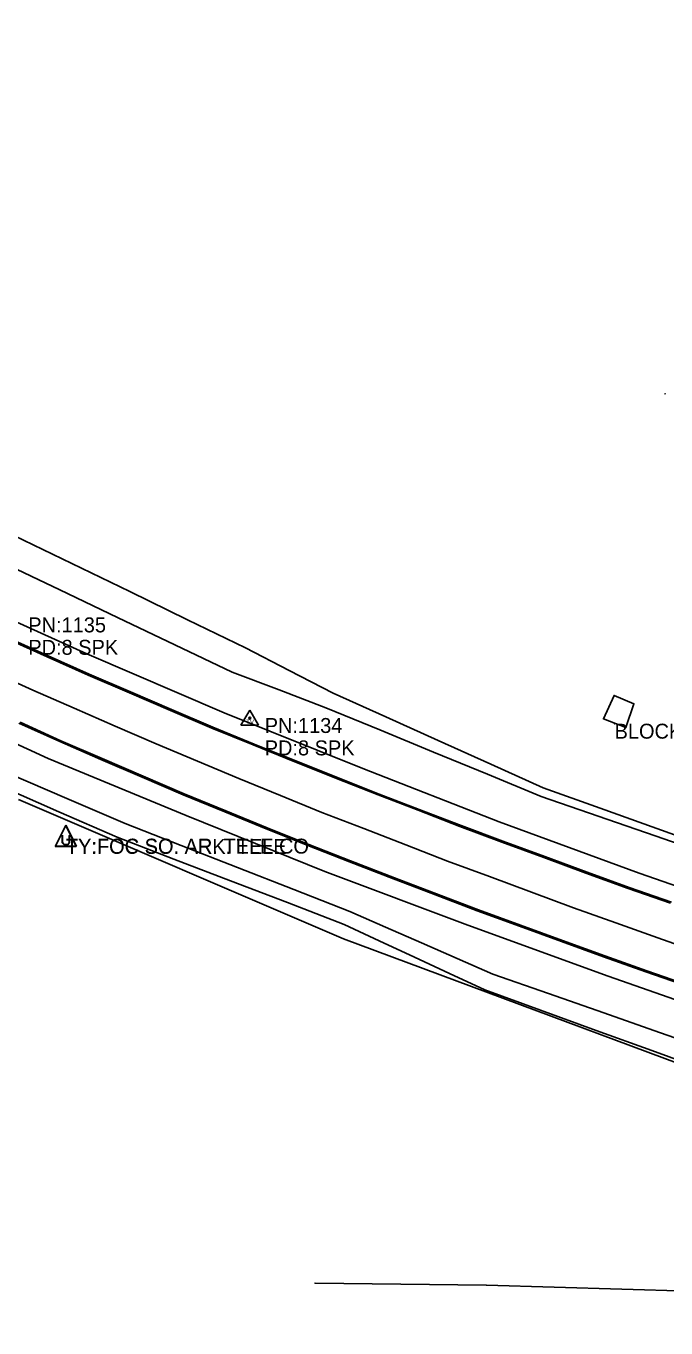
# Model space of a CAD drawing. Extents: x 878399 to 889864, y 1564003 to 1567413.
# Drawn here: x 885851.5 to 886065.8, y 1564498.7 to 1564934.4 of the extents above; entities that cross this region are included whole.
import ezdxf

# ---------------------------------------------------------------- set-up
doc = ezdxf.new("R2010")
doc.units = 0
for name, color, linetype in [('S_BUILDING', 7, 'Continuous'), ('S_DITCHLINE', 7, 'Continuous'), ('S_EDGE_PAVEMENT', 7, 'Continuous'), ('S_FENCE', 7, 'Continuous'), ('S_FIBER_OPTIC_CABLE', 7, 'Continuous'), ('S_MSC_PT_SYM', 7, 'Continuous'), ('S_PAVEMENT_CROWN', 7, 'Continuous'), ('S_SECONDARY_CTL', 7, 'Continuous'), ('S_SECONDARY_CTL_ANNOT', 7, 'Continuous'), ('S_SHOULDER', 7, 'Continuous'), ('S_STR_PT_SYM', 7, 'Continuous'), ('S_SURVEY_TEXT_ANNOT', 7, 'Continuous'), ('S_UTILITY_POLE', 7, 'Continuous'), ('S_UTILITY_POLE_ANNOT', 7, 'Continuous'), ('S_UTL_PT_SYM', 7, 'Continuous')]:
    doc.layers.add(name, color=color, linetype=linetype)

msp = doc.modelspace()

# ---------------------------------------------------------------- linework, layer by layer
at = {"layer": 'S_BUILDING'}
for p, q in [((886044.86, 1564702.57), (886048.48, 1564710.41)), ((886048.48, 1564710.41), (886055.08, 1564707.59)), ((886055.08, 1564707.59), (886052.38, 1564699.65)), ((886052.38, 1564699.65), (886044.86, 1564702.57))]:
    msp.add_line(p, q, dxfattribs=at)
at = {"layer": 'S_DITCHLINE'}
for points in [[(886151.69, 1564635.57), (886138.96, 1564639.73), (886126.22, 1564643.88), (886113.49, 1564648.04), (886100.75, 1564652.2), (886081.74, 1564659.01), (886062.72, 1564665.83), (886043.71, 1564672.65), (886024.7, 1564679.47), (886007.11, 1564687.39), (885989.52, 1564695.32), (885971.94, 1564703.24), (885954.35, 1564711.17), (885939.66, 1564718.75), (885924.96, 1564726.34), (885905.6, 1564735.73), (885886.23, 1564745.12), (885866.86, 1564754.51), (885847.49, 1564763.9)], [(886150.93, 1564634.01), (886138.26, 1564638.06), (886125.58, 1564642.1), (886112.9, 1564646.14), (886100.22, 1564650.18), (886081.18, 1564656.77), (886062.13, 1564663.36), (886043.09, 1564669.96), (886024.05, 1564676.55), (886006.01, 1564683.98), (885987.98, 1564691.41), (885969.95, 1564698.83), (885951.91, 1564706.26), (885936.25, 1564712.21), (885920.59, 1564718.15), (885901.35, 1564727.33), (885882.11, 1564736.51), (885862.87, 1564745.69), (885843.63, 1564754.86)], [(886082.21, 1564591.11), (886063.62, 1564597.61), (886045.03, 1564604.11), (886026.43, 1564610.61), (886007.84, 1564617.11), (885995.87, 1564622.36), (885983.9, 1564627.6), (885971.93, 1564632.85), (885959.96, 1564638.09), (885941.14, 1564645.44), (885922.33, 1564652.78), (885903.52, 1564660.12), (885884.7, 1564667.47), (885865.23, 1564675.86), (885845.75, 1564684.26)], [(886079.66, 1564584.7), (886061.03, 1564591.49), (886042.4, 1564598.27), (886023.77, 1564605.06), (886005.15, 1564611.84), (885993.36, 1564617.31), (885981.58, 1564622.79), (885969.8, 1564628.26), (885958.02, 1564633.74), (885939.03, 1564641.03), (885920.04, 1564648.31), (885901.05, 1564655.6), (885882.06, 1564662.89), (885862.55, 1564671.47), (885843.04, 1564680.05)]]:
    msp.add_lwpolyline(points, dxfattribs=at)
at = {"layer": 'S_EDGE_PAVEMENT'}
for points in [[(885844.95, 1564729.45), (885858.63, 1564723.28), (885872.33, 1564717.17), (885886.12, 1564711.26), (885899.91, 1564705.36), (885913.7, 1564699.46), (885927.6, 1564693.8), (885927.6, 1564693.8), (885927.6, 1564693.8), (885941.51, 1564688.18), (885941.51, 1564688.18), (885955.42, 1564682.55), (885969.39, 1564677.07), (885982.79, 1564671.94), (885996.8, 1564666.57), (886010.83, 1564661.25), (886024.92, 1564656.09), (886039.01, 1564650.94), (886053.09, 1564645.79), (886067.25, 1564640.82)], [(885845.31, 1564729.77), (885858.99, 1564723.6), (885872.69, 1564717.49), (885886.48, 1564711.59), (885900.27, 1564705.68), (885914.06, 1564699.78), (885927.96, 1564694.12), (885927.96, 1564694.12), (885927.96, 1564694.12), (885941.86, 1564688.5), (885941.86, 1564688.5), (885955.77, 1564682.88), (885969.74, 1564677.39), (885983.14, 1564672.26), (885997.16, 1564666.89), (886011.18, 1564661.57), (886025.27, 1564656.42), (886039.36, 1564651.26), (886053.44, 1564646.11), (886067.6, 1564641.14)], [(885849.15, 1564701.07), (885862.83, 1564694.91), (885862.83, 1564694.91), (885862.83, 1564694.91), (885876.61, 1564688.98), (885876.61, 1564688.98), (885890.39, 1564683.05), (885890.39, 1564683.05), (885890.39, 1564683.05), (885904.17, 1564677.11), (885918.05, 1564671.41), (885918.05, 1564671.41), (885918.05, 1564671.41), (885931.96, 1564665.79), (885931.96, 1564665.79), (885945.87, 1564660.17), (885945.87, 1564660.17), (885945.87, 1564660.17), (885959.83, 1564654.66), (885974.58, 1564649.01), (885988.6, 1564643.64), (886002.62, 1564638.3), (886016.71, 1564633.17), (886030.81, 1564628.04), (886030.81, 1564628.04), (886044.91, 1564622.92), (886044.91, 1564622.92), (886044.91, 1564622.92), (886059.05, 1564617.92), (886073.21, 1564612.97)], [(885849.51, 1564701.39), (885863.19, 1564695.24), (885863.19, 1564695.24), (885863.19, 1564695.24), (885876.97, 1564689.3), (885876.97, 1564689.3), (885890.75, 1564683.37), (885890.75, 1564683.37), (885890.75, 1564683.37), (885904.52, 1564677.43), (885918.4, 1564671.74), (885918.4, 1564671.74), (885918.4, 1564671.74), (885932.31, 1564666.12), (885932.31, 1564666.12), (885946.22, 1564660.5), (885946.22, 1564660.5), (885946.22, 1564660.5), (885960.18, 1564654.99), (885974.94, 1564649.33), (885988.95, 1564643.97), (886002.97, 1564638.63), (886017.07, 1564633.5), (886031.16, 1564628.37), (886031.16, 1564628.37), (886045.26, 1564623.24), (886045.26, 1564623.24), (886045.26, 1564623.24), (886059.4, 1564618.25), (886073.56, 1564613.3)]]:
    msp.add_lwpolyline(points, dxfattribs=at)
at = {"layer": 'S_FENCE'}
for p, q in [((886005.69, 1564513.05), (885948.3, 1564513.63)), ((886073.61, 1564510.98), (886005.69, 1564513.05))]:
    msp.add_line(p, q, dxfattribs=at)
at = {"layer": 'S_FIBER_OPTIC_CABLE'}
for p, q in [((885957.86, 1564628.9), (885849.03, 1564675.55)), ((886070.21, 1564587.13), (885957.86, 1564628.9))]:
    msp.add_line(p, q, dxfattribs=at)
at = {"layer": 'S_MSC_PT_SYM'}
for points in [[(886065.49, 1564811.37), (886065.49, 1564811.42), (886065.49, 1564811.37), (886065.44, 1564811.37), (886065.49, 1564811.37), (886065.49, 1564811.32), (886065.49, 1564811.37), (886065.54, 1564811.37)], [(886048.58, 1564700.92), (886048.58, 1564700.97), (886048.58, 1564700.92), (886048.53, 1564700.92), (886048.58, 1564700.92), (886048.58, 1564700.87), (886048.58, 1564700.92), (886048.63, 1564700.92)], [(885948.3, 1564513.63), (885948.3, 1564513.68), (885948.3, 1564513.63), (885948.25, 1564513.63), (885948.3, 1564513.63), (885948.3, 1564513.58), (885948.3, 1564513.63), (885948.35, 1564513.63)], [(886005.69, 1564513.05), (886005.69, 1564513.1), (886005.69, 1564513.05), (886005.64, 1564513.05), (886005.69, 1564513.05), (886005.69, 1564513), (886005.69, 1564513.05), (886005.74, 1564513.05)]]:
    msp.add_lwpolyline(points, dxfattribs=at)
at = {"layer": 'S_PAVEMENT_CROWN'}
msp.add_lwpolyline([(885840.21, 1564718.33), (885853.86, 1564712.09), (885867.61, 1564706.1), (885881.37, 1564700.13), (885895.13, 1564694.16), (885908.96, 1564688.33), (885922.83, 1564682.61), (885936.69, 1564676.89), (885950.59, 1564671.25), (885964.59, 1564665.82), (885978.65, 1564660.38), (885992.65, 1564654.96), (886006.71, 1564649.73), (886020.78, 1564644.52), (886034.84, 1564639.31), (886048.96, 1564634.22), (886063.1, 1564629.23), (886077.25, 1564624.23)], dxfattribs=at)
at = {"layer": 'S_SECONDARY_CTL'}
for p, q in [((885926.43, 1564705.43), (885923.42, 1564700.47)), ((885926.43, 1564705.43), (885929.37, 1564700.47)), ((885923.42, 1564700.47), (885929.37, 1564700.47))]:
    msp.add_line(p, q, dxfattribs=at)
for radius in [0.311, 0.183, 0.103]:
    msp.add_circle((885926.43, 1564702.82), radius, dxfattribs=at)
at = {"layer": 'S_SHOULDER'}
for points in [[(885477.34, 1564934.42), (885519.82, 1564908.04), (885562.37, 1564882.88), (885605.78, 1564858.06), (885649.01, 1564834.13), (885693.1, 1564810.55), (885737.12, 1564788.02), (885781.98, 1564765.92), (885827.15, 1564744.48), (885871.93, 1564724.36), (885917.84, 1564704.55), (885964.25, 1564685.89), (886009.9, 1564668.12), (886056.86, 1564650.94), (886104.07, 1564634.45), (886150.87, 1564618.86), (886198.78, 1564604.53), (886245.81, 1564590.69), (886294.03, 1564577.4), (886342.52, 1564565.18), (886391.29, 1564554.1), (886439.19, 1564543.9), (886488.35, 1564534.77)], [(885502.12, 1564876.69), (885545.5, 1564850.36), (885589.04, 1564825.78), (885633.6, 1564801.51), (885677.62, 1564777.79), (885722.81, 1564754.83), (885767.3, 1564732.01), (885812.49, 1564710.58), (885858.95, 1564689.25), (885905.17, 1564670.16), (885951.57, 1564651.51), (885999.47, 1564633.52), (886046.46, 1564616.42), (886093.66, 1564599.92), (886142, 1564584.31), (886189.76, 1564569.49), (886238.85, 1564555.08), (886286.99, 1564541.47), (886335.49, 1564529.28), (886384.19, 1564517.92), (886434.5, 1564507.62), (886483.69, 1564498.68)]]:
    msp.add_lwpolyline(points, dxfattribs=at)
at = {"layer": 'S_STR_PT_SYM'}
for points in [[(886048.48, 1564710.41), (886048.48, 1564710.46), (886048.48, 1564710.41), (886048.43, 1564710.41), (886048.48, 1564710.41), (886048.48, 1564710.36), (886048.48, 1564710.41), (886048.53, 1564710.41)], [(886055.08, 1564707.59), (886055.08, 1564707.64), (886055.08, 1564707.59), (886055.03, 1564707.59), (886055.08, 1564707.59), (886055.08, 1564707.54), (886055.08, 1564707.59), (886055.13, 1564707.59)], [(886044.86, 1564702.57), (886044.86, 1564702.62), (886044.86, 1564702.57), (886044.81, 1564702.57), (886044.86, 1564702.57), (886044.86, 1564702.52), (886044.86, 1564702.57), (886044.91, 1564702.57)], [(886052.38, 1564699.65), (886052.38, 1564699.7), (886052.38, 1564699.65), (886052.33, 1564699.65), (886052.38, 1564699.65), (886052.38, 1564699.6), (886052.38, 1564699.65), (886052.43, 1564699.65)]]:
    msp.add_lwpolyline(points, dxfattribs=at)
at = {"layer": 'S_UTILITY_POLE'}
for p, q in [((885864.85, 1564666.89), (885861.32, 1564659.8)), ((885864.89, 1564666.98), (885861.36, 1564659.89)), ((885864.85, 1564666.89), (885868.34, 1564659.8)), ((885864.89, 1564666.98), (885868.38, 1564659.89)), ((885863.65, 1564661.04), (885863.65, 1564663.48)), ((885864.27, 1564660.38), (885863.65, 1564661.04)), ((885863.69, 1564661.13), (885863.69, 1564663.57)), ((885864.31, 1564660.47), (885863.69, 1564661.13)), ((885865.51, 1564660.47), (885864.31, 1564660.47)), ((885866.01, 1564661.04), (885865.47, 1564660.38)), ((885866.05, 1564661.13), (885865.51, 1564660.47)), ((885866.01, 1564663.48), (885866.01, 1564661.04)), ((885866.05, 1564663.57), (885866.05, 1564661.13)), ((885861.32, 1564659.8), (885868.34, 1564659.8)), ((885861.36, 1564659.89), (885868.38, 1564659.89)), ((885865.47, 1564660.38), (885864.27, 1564660.38))]:
    msp.add_line(p, q, dxfattribs=at)
at = {"layer": 'S_UTL_PT_SYM'}
msp.add_lwpolyline([(885957.86, 1564628.9), (885957.86, 1564628.95), (885957.86, 1564628.9), (885957.81, 1564628.9), (885957.86, 1564628.9), (885957.86, 1564628.85), (885957.86, 1564628.9), (885957.91, 1564628.9)], dxfattribs=at)

# ---------------------------------------------------------------- texts
at = {"layer": 'S_SECONDARY_CTL'}
msp.add_text('TV', height=1.5, rotation=360, dxfattribs=at).set_placement((885925.22, 1564700.81))
at = {"layer": 'S_SECONDARY_CTL_ANNOT'}
for s, p in [('PN:1135', (885852.28, 1564731.49)), ('PD:8 SPK', (885852.28, 1564723.99)), ('PN:1134', (885931.43, 1564697.82)), ('PD:8 SPK', (885931.43, 1564690.32))]:
    msp.add_text(s, height=5, dxfattribs=at).set_placement(p)
at = {"layer": 'S_SURVEY_TEXT_ANNOT'}
msp.add_text('BLOCK WELL HOUSE', height=5, dxfattribs=at).set_placement((886048.58, 1564695.92))
at = {"layer": 'S_UTILITY_POLE_ANNOT'}
for s, p in [('TY:FOC SO. ARK. TELE', (885864.85, 1564657.36)), ('TY:FOC SO. AR. TELE CO', (885864.89, 1564657.44))]:
    msp.add_text(s, height=5, dxfattribs=at).set_placement(p)

doc.saveas('drawing.dxf')
